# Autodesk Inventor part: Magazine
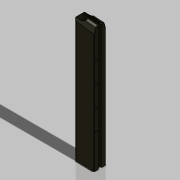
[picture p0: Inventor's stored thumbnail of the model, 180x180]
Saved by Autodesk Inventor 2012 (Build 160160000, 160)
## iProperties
Company: MH Vaaben Teknik
Category: Sten MK II Magazine
Created: 2011-12
Part Number: Magazine
Material: Steel, Mild
Document SubType Name: Modeling
Designer: Michael Høgh
Density: 7.86 g/cm^3
Project: Steen MK II
Engineer: MH Vaaben Teknik
Mass: 208.54 g
Surface Area: 532.818 cm^2
Volume: 26.5318 cm^3
Author: Michael Høgh
Title: Magazine
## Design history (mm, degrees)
sketch "Sketch1"
  geometry: L1 (19, 10.75)-(19, -10.75); L2 (-19, -6.633)-(-19, 6.633); L3 (19, 10.75)-(-15.884, 9.832); L4 (-25.821, 0)-(36.623, 0); L5 (19, -10.75)-(-15.884, -9.832); A1 r 3.2 centre (-15.8, 6.633) between (-15.884, 9.832) and (-19, 6.633); A2 r 3.2 centre (-15.8, -6.633) between (-19, -6.633) and (-15.884, -9.832); 2 further points
  constraints: 10 end point, 4 point on circle, 4 tangent, 2 centre point, 1 horizontal alignment, 1 midpoint, 1 parallel, 1 perpendicular
  dimensions: "d1" = 21.5 distance of L1.start L1.end; "d4" = 38 distance between parallel lines of L1 L2; "d9" = 1.5074 deg angle of L3 L4; "d10" = 1.5074 deg angle of L5 L4; "d14" = 6.4 diameter of A1; "d15" = 6.4 diameter of A2
extrude "Extrusion2" new body sketch "Sketch1" distance "d16" = 234; taper "d17" = 0 deg
sketch "Sketch3"
  geometry: L1 (-19, -10.75)-(-19, 10.75) reference; C1 r 3.2 at (-19, 0); 1 further point
  constraints: 1 centre point, 1 midpoint
  dimensions: "d18" = 6.4 diameter of C1
extrude "Extrusion3" cut sketch "Sketch3" stored distance "d19" = 234; taper "d20" = 0 deg
sketch "Sketch4"
  geometry: L1 (0, 7.55)-(0, 0) reference; L2 (234, 0)-(0, 0) reference; L3 (12, 0)-(0, 3.215); L4 (234, 21.5)-(0, 21.5) reference; L5 (12, 21.5)-(0, 18.285); L6 (12, 21.5)-(26.251, 21.5); L7 (0, 18.285)-(0, 21.5); L8 (0, 3.215)-(0, 0); L9 (0, 21.5)-(12, 21.5); L10 (0, 20.582)-(0, 21.5) reference; L11 (0, 0)-(12, 0); L12 (0, 0)-(0, 0.918) reference; 1 further point
  constraints: 14 end point, 3 perpendicular, 3 point on line, 1 collinear, 1 horizontal
  dimensions: "d21" = 12 distance from line of L3.start L1; "d22" = 15 deg angle of L3 L2; "d24" = 15 deg angle of L5 L4; "d25" = 12 distance of L5.start L4.end
extrude "Extrusion4" cut sketch "Sketch4" stored distance "d26" = 234; taper "d27" = 0 deg
fillet "Fillet1" dims "d30" = 1
sketch "Sketch6"
  geometry: L1 (-18.87, -7.535)-(19, -7.535) reference; L2 (19, 7.535)-(-19, 7.535); L3 (-19, 7.535)-(-19, -7.535); L4 (-19, -7.535)-(19, -7.535); L5 (19, -7.535)-(19, 7.535); L6 (-19, -6.633)-(-19, 6.633) reference; 1 further point
  constraints: 8 end point, 2 parallel, 1 horizontal, 1 perpendicular, 1 point on line
  dimensions: "d40" = 0 distance between parallel lines of L6 L3
extrude "Extrusion6" join sketch "Sketch6" distance "d38" = 1.5; taper "d39" = 0 deg
sketch "Sketch7"
  geometry: L1 (0, 0)-(-8.168, -2.189) reference; L2 (-9.668, -2.189)-(-9.668, -17.258) reference; L3 (-8.168, -17.258)-(-9.668, -17.258) reference; L4 (-8.168, -17.258)-(0, -19.447) reference; L5 (-8.168, -17.258)-(-9.668, -16.856); L6 (-9.668, -16.856)-(-9.668, -17.258); L7 (-8.168, -17.258)-(-9.668, -17.258); L8 (-8.168, -2.189)-(-9.668, -2.591); L9 (-9.668, -2.591)-(-9.668, -2.189); L10 (-8.168, -2.189)-(-9.668, -2.189); 1 further point
  constraints: 12 end point, 4 perpendicular, 1 collinear, 1 point on line
  dimensions: "d41" = 0 distance between parallel lines of L6 L2; "d42" = 0 distance between parallel lines of L9 L2
extrude "Extrusion7" cut sketch "Sketch7" stored distance "d43" = 1.5; taper "d44" = 0 deg
workplane "Work Plane Left"
sketch "Sketch8"
  geometry: L1 (-235.5, 1.026)-(-235.5, -17.474); L2 (-235.5, 1.026)-(-235.5, -36.974) reference; L3 (-235.5, -17.474)-(-234, 1.026); L4 (-225.832, 1.026)-(-235.5, 1.026) reference; L5 (-235.5, 1.026)-(-234, 1.026); 1 further point
  constraints: 6 end point, 2 point on line, 1 collinear
  dimensions: "d46" = 18.5 distance of L1.start L1.end; "d47" = 1.5 distance of L1.start L3.end
extrude "Extrusion8" cut sketch "Sketch8" stored distance "d48" = 1.5; taper "d49" = 0 deg
fillet "Fillet2" dims "d50" = 4.4
fillet "Fillet4" dims "d52" = 1
sketch "Sketch9"
  geometry: L1 (-18.387, -3.141)-(-18.387, 3.141) reference; C1 r 3.2 at (-19, 0); A1 r 3.2 centre (-19, 0) between (-18.387, -3.141) and (-18.387, 3.141) reference; 1 further point
  constraints: 1 centre point, 1 coincident, 1 concentric
extrude "Extrusion9" cut sketch "Sketch9" distance "d53" = 1.5; taper "d54" = 0 deg
shell "Shell3" dims "d55" = 1
sketch "Sketch10"
  geometry: C1 r 4.4 at (-235, 9.723); 1 further point
  constraints: 1 centre point
  dimensions: "d56" = 8.8 diameter of C1; "d57" = 235 distance of C1.centre point (0, 9.723)
extrude "Extrusion10" cut sketch "Sketch10" stored distance "d58" = 1.5; taper "d59" = 0 deg
sketch "Sketch11"
  geometry: L1 (-221.968, 1.026)-(-230.547, 1.026) reference; L2 (-230.4, -27.224)-(-230.4, -39.9); L3 (-230.4, -39.9)-(-243.875, -39.9); L4 (-235.5, -35.936)-(-235.5, -18.036) reference; A1 r 12.7 centre (-243.1, -27.224) between (-230.4, -27.224) and (-243.875, -39.9); 1 further point
  constraints: 4 end point, 2 perpendicular, 2 point on circle, 1 centre point, 1 tangent
  dimensions: "d60" = 25.4 diameter of A1; "d61" = 28.25 distance from line of A1.centre L1; "d62" = 5.1 distance between parallel lines of L2 L4
extrude "Extrusion11" cut sketch "Sketch11" stored distance "d63" = 0; taper "d64" = 0 deg
chamfer "Chamfer1" distance "d65" = 0.1; stored, may be unused: second distance "d66" = 2, angle "d67" = 45 deg
fillet "Fillet5" dims "d68" = 0.2
sketch "Sketch12"
  geometry: L1 (33.87, 221.968)-(33.87, 0) reference; L2 (0, 0)-(33.87, 0); L3 (33.87, 0)-(33.87, 1); L4 (33.87, 1)-(0, 1); L5 (0, 1)-(0, 0); 1 further point
  constraints: 8 end point, 2 parallel, 1 horizontal, 1 perpendicular, 1 point on line
  dimensions: "d69" = 1 distance of L3.end L2.end
extrude "Extrusion12" join sketch "Sketch12" distance "d70" = 2; taper "d71" = 0 deg
sketch "Sketch13"
  geometry: L1 (0, 225.293)-(0, 0) reference; L2 (33.87, 225.293)-(0, 225.293); L3 (0, 225.293)-(0, 224.293); L4 (0, 224.293)-(33.87, 224.293); L5 (33.87, 224.293)-(33.87, 225.293); 1 further point
  constraints: 8 end point, 2 parallel, 1 horizontal, 1 perpendicular, 1 point on line
  dimensions: "d72" = 1 distance of L3.end L2.end
extrude "Extrusion13" join sketch "Sketch13" distance "d73" = 2; taper "d74" = 0 deg
fillet "Fillet7" dims "d76" = 0.5
chamfer "Chamfer2" distance "d78" = 0.1; stored, may be unused: second distance "d79" = 2, angle "d80" = 45 deg
fillet "Fillet9" dims "d84" = 0.5
chamfer "Chamfer4" distance "d85" = 0.1; stored, may be unused: second distance "d86" = 2, angle "d87" = 45 deg
chamfer "Chamfer5" distance "d88" = 0.1; stored, may be unused: second distance "d89" = 2, angle "d90" = 45 deg
fillet "Fillet10" dims "d91" = 0.4
sketch "Sketch14"
  geometry: L1 (-221.868, -1)-(-0.4, -1) reference; L2 (0, 3.09)-(-230.2, 3.09) reference; C1 r 2 at (-176.9, 3.2); C2 r 2 at (-138.9, 3.09); C3 r 2 at (-100.9, 3.09); C4 r 2 at (-62.9, 3.09); 3 further points
  constraints: 4 centre point, 3 point on line
  dimensions: "d92" = 4 diameter of C1; "d93" = 4.2 distance from line of C1.centre L1; "d101" = 4 diameter of C2; "d102" = 4 diameter of C3; "d103" = 4 diameter of C4; "d104" = 38 horizontal distance of C2.centre C1.centre; "d105" = 38 distance of C3.centre C2.centre; "d106" = 38 distance of C4.centre C3.centre; "d107" = 63 horizontal distance of point (0.1, 9.723) C4.centre
extrude "Extrusion14" cut sketch "Sketch14" stored distance "d108" = 10; taper "d109" = 0 deg
chamfer "Chamfer6" distance "d110" = 0.1; stored, may be unused: second distance "d111" = 2, angle "d112" = 45 deg
body "Solid2"
fillet "Fillet6" dims "d113" = 2
other parameters: "d45" = 90 deg
